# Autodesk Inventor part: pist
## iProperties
Shininess: 64.0
Length Units: 11269
Angle Units: 11279
Time Units: 11290
Mass Units: 11283
Length Display Precision: 3
Angle Display Precision: 2
Compacted: True
Part Number: pist
Document SubType Name: Modeling
Created: 2003-06
Material: Výchozí
Density: 0.0
Volumn: 0.0
Area: 0.0
PropertySet Name: Model Information
Control State: 0
Master: False
Checked Out: False
Title: pist
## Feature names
1. Vysunutí1 [Extrusion]
2. Vysunutí2 [Extrusion]
3. Vysunutí3 [Extrusion]
